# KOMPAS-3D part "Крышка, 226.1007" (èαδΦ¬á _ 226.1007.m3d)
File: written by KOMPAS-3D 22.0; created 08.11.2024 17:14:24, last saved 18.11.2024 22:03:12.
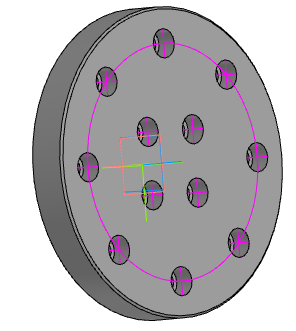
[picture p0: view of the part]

Document properties: Автор: aleksander.larionov.10@gmail.com; Полное имя файла: C:\Мои папки\Работа\Крышки, фланцы\226.1007\Крышка _ 226.1007.m3d

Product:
- Part/product: Крышка  | designation 226.1007
    Материал: Сталь 45 ГОСТ 1050-2013 (density 7810 kg/m3)
    Масса: 16.202065

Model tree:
1. Эскиз:1
2. Элемент выдавливания:1
     Расстояние 1 = 38
3. Эскиз:2  (with: Элемент выдавливания:1)
4. Отверстие:1  (with: Элемент выдавливания:1)
     Глубина выреза = 38; Диаметр отверстия = 18; Угол конуса дна = 118; Расстояние 1 = 105; Диаметр цековки = 26; Глубина цековки = 19
5. Массив по точкам:1
6. Экземпляр ( 11 )  (with: Отверстие:1)
7. Экземпляр ( 7 )  (with: Отверстие:1)
8. Экземпляр ( 5 )  (with: Отверстие:1)
9. Экземпляр ( 6 )  (with: Отверстие:1)
10. Экземпляр ( 3 )  (with: Отверстие:1)
11. Экземпляр ( 1 )  (with: Отверстие:1)
12. Экземпляр ( 9 )  (with: Отверстие:1)
13. Экземпляр ( 4 )  (with: Отверстие:1)
14. Экземпляр ( 8 )  (with: Отверстие:1)
15. Экземпляр ( 2 )  (with: Отверстие:1)
16. Экземпляр ( 10 )  (with: Отверстие:1)
17. Фаска:1  (with: Элемент выдавливания:1)  (labels: Сталь 45 ГОСТ 1050-2013)
     Угол = 45; Длина 1 = 2; Длина 2 = 2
